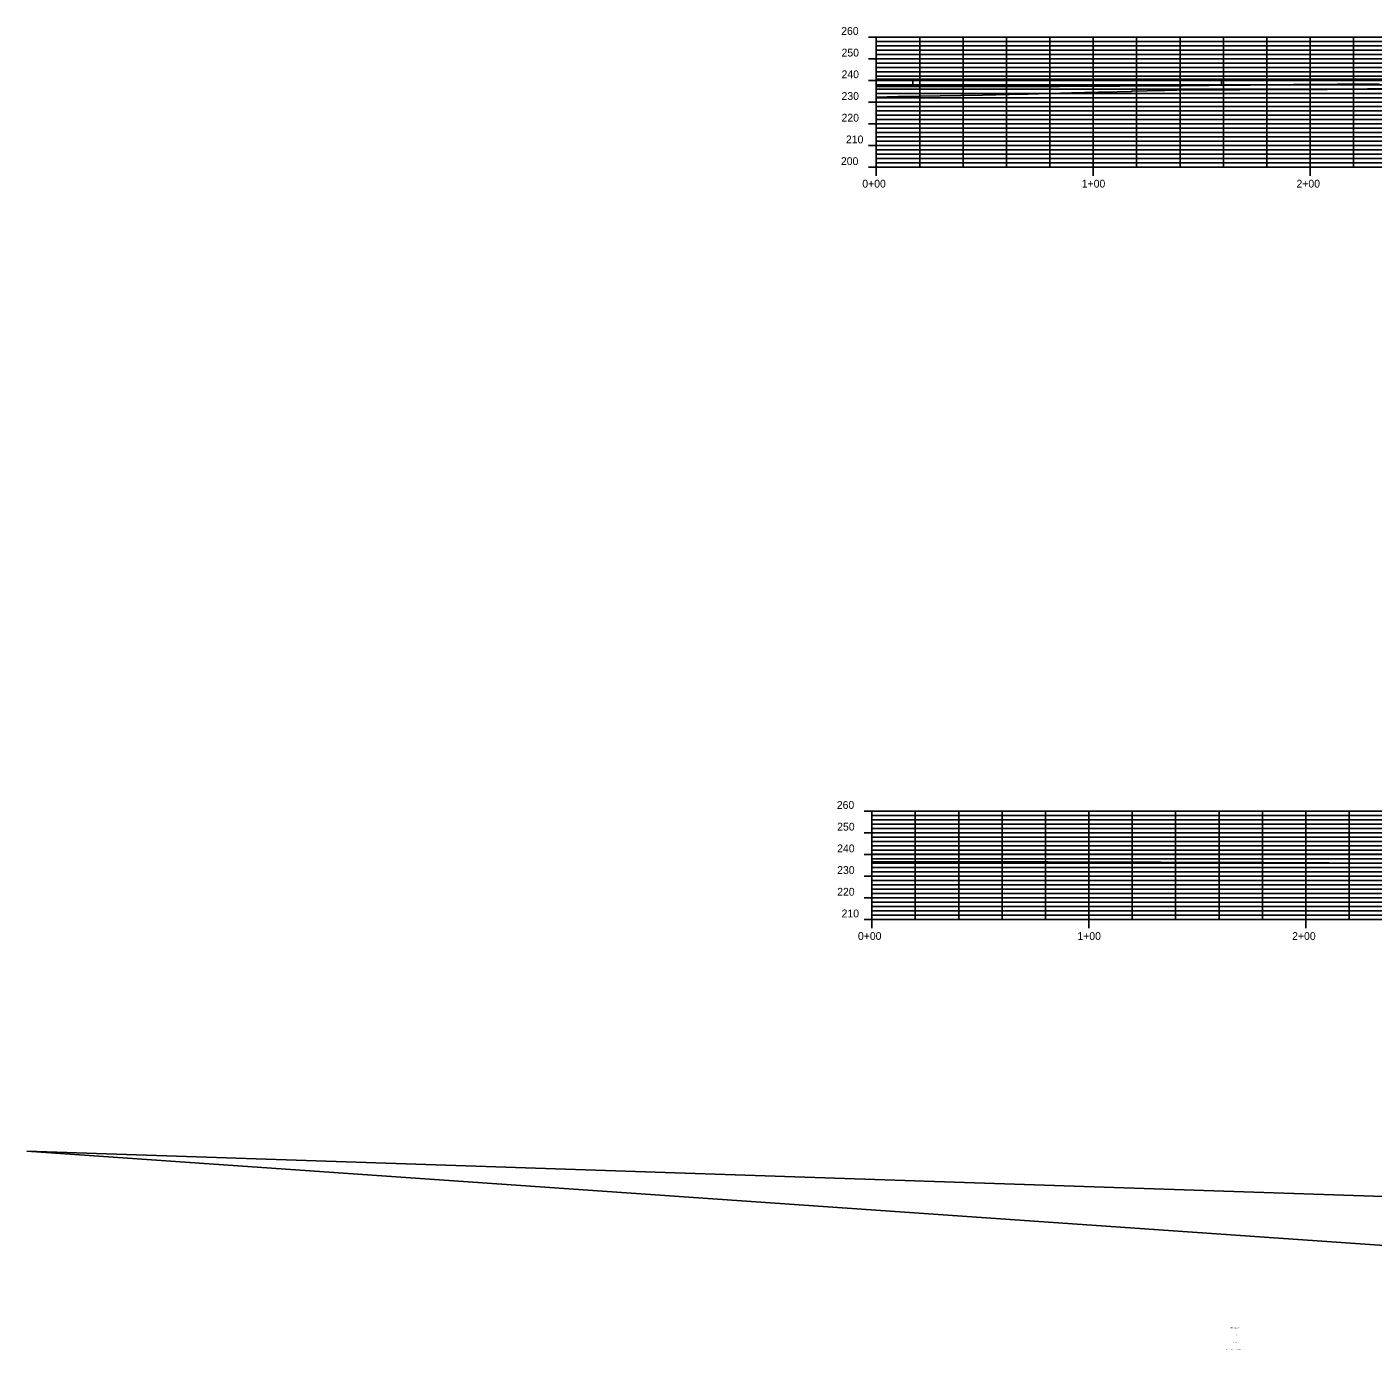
# Model space of a CAD drawing. Extents: x 977011 to 983719, y 1526280 to 1528290.
# Drawn here: x 977011 to 977632, y 1527680 to 1528290 of the extents above; entities that cross this region are included whole.
import ezdxf

# ---------------------------------------------------------------- set-up
doc = ezdxf.new("R2010")
doc.units = 0
for name, color, linetype in [('B_Concrete', 7, 'Continuous'), ('R_Axis', 7, 'Continuous'), ('R_Axis Annot', 7, 'Continuous'), ('R_Exist Surface', 7, 'Continuous'), ('R_Grid', 7, 'Continuous'), ('R_Vert Alg', 7, 'Continuous')]:
    doc.layers.add(name, color=color, linetype=linetype)

msp = doc.modelspace()

# ---------------------------------------------------------------- linework, layer by layer
at = {"layer": 'B_Concrete'}
for p, q in [((977402.95, 1528265.57), (977976.87, 1528265.62)), ((977402.95, 1528262.07), (977402.95, 1528265.57)), ((977419.82, 1528262.09), (977419.82, 1528264.76)), ((977562.03, 1528262.66), (977562.03, 1528265.33)), ((978067.84, 1527908.78), (977400.94, 1527908.34)), ((977400.94, 1527904.84), (977400.94, 1527908.34)), ((977011.43, 1527771.4), (977676.06, 1527749.18)), ((977676.72, 1527725.15), (977011.43, 1527771.4))]:
    msp.add_line(p, q, dxfattribs=at)
at = {"layer": 'R_Axis'}
for p, q in [((977402.95, 1528224.95), (977402.95, 1528284.95)), ((977402.95, 1528224.95), (978002.95, 1528224.95)), ((977400.94, 1527878.16), (977400.94, 1527928.16)), ((977400.94, 1527878.16), (978100.94, 1527878.16))]:
    msp.add_line(p, q, dxfattribs=at)
at = {"layer": 'R_Exist Surface'}
for points in [[(977402.95, 1528257.29), (977413.01, 1528257.5), (977423.35, 1528257.69), (977432.4, 1528257.82), (977441.87, 1528257.99), (977451.91, 1528258.14), (977464.26, 1528258.45), (977472.89, 1528258.65), (977487.9, 1528259.03), (977492.87, 1528259.15), (977505.2, 1528259.47), (977507.5, 1528259.51), (977520.39, 1528259.86), (977520.96, 1528259.92), (977534.73, 1528260.31), (977536.02, 1528260.35), (977547.2, 1528260.53), (977560.09, 1528260.58), (977563.18, 1528260.64), (977570.45, 1528260.62), (977576.87, 1528260.72), (977578.22, 1528260.7), (977592.31, 1528260.8), (977592.65, 1528260.8), (977593.75, 1528260.8), (977607.35, 1528260.81), (977610.8, 1528260.81), (977614.69, 1528260.84), (977620.87, 1528260.93), (977629.34, 1528261), (977637.08, 1528261.02)], [(977400.94, 1527904.84), (977401.53, 1527904.84), (977404.17, 1527904.83), (977416.54, 1527904.81), (977419.65, 1527904.8), (977431.56, 1527904.78), (977431.76, 1527904.78), (977434.59, 1527904.77), (977445.24, 1527904.76), (977446.5, 1527904.75), (977448.13, 1527904.75), (977461.51, 1527904.73), (977468.14, 1527904.73), (977473.58, 1527904.74), (977476.51, 1527904.73), (977479.11, 1527904.72), (977482.19, 1527904.71), (977491.61, 1527904.68), (977494.79, 1527904.67), (977503, 1527904.67), (977506.16, 1527904.67), (977506.62, 1527904.66), (977520.43, 1527904.61), (977521.63, 1527904.6), (977534.09, 1527904.55), (977536.65, 1527904.52), (977547.72, 1527904.48), (977551.66, 1527904.48), (977561.81, 1527904.45), (977566.67, 1527904.44), (977571.91, 1527904.43), (977581.6, 1527904.39), (977589.95, 1527904.36), (977596.61, 1527904.33), (977604.4, 1527904.29), (977611.62, 1527904.26), (977620.68, 1527904.21), (977626.63, 1527904.18), (977631.7, 1527904.16), (977641.64, 1527904.14)]]:
    msp.add_lwpolyline(points, dxfattribs=at)
at = {"layer": 'R_Grid'}
for p, q in [((977399.35, 1528284.95), (977402.95, 1528284.95)), ((977399.35, 1528284.95), (977402.95, 1528284.95)), ((977402.95, 1528284.95), (978002.95, 1528284.95)), ((977402.95, 1528284.95), (978002.95, 1528284.95)), ((977422.95, 1528224.95), (977422.95, 1528284.95)), ((977442.95, 1528224.95), (977442.95, 1528284.95)), ((977462.95, 1528224.95), (977462.95, 1528284.95)), ((977482.95, 1528224.95), (977482.95, 1528284.95)), ((977502.95, 1528224.95), (977502.95, 1528284.95)), ((977522.95, 1528224.95), (977522.95, 1528284.95)), ((977542.95, 1528224.95), (977542.95, 1528284.95)), ((977562.95, 1528224.95), (977562.95, 1528284.95)), ((977582.95, 1528224.95), (977582.95, 1528284.95)), ((977602.95, 1528224.95), (977602.95, 1528284.95)), ((977622.95, 1528224.95), (977622.95, 1528284.95)), ((977402.95, 1528282.95), (977404.75, 1528282.95)), ((977402.95, 1528282.95), (978002.95, 1528282.95)), ((977402.95, 1528280.95), (977404.75, 1528280.95)), ((977402.95, 1528280.95), (978002.95, 1528280.95)), ((977402.95, 1528278.95), (977404.75, 1528278.95)), ((977402.95, 1528278.95), (978002.95, 1528278.95)), ((977399.35, 1528274.95), (977402.95, 1528274.95)), ((977402.95, 1528276.95), (977404.75, 1528276.95)), ((977402.95, 1528276.95), (978002.95, 1528276.95)), ((977402.95, 1528274.95), (978002.95, 1528274.95)), ((977402.95, 1528272.95), (977404.75, 1528272.95)), ((977402.95, 1528272.95), (978002.95, 1528272.95)), ((977402.95, 1528270.95), (977404.75, 1528270.95)), ((977402.95, 1528270.95), (978002.95, 1528270.95)), ((977402.95, 1528268.95), (977404.75, 1528268.95)), ((977402.95, 1528268.95), (978002.95, 1528268.95)), ((977402.95, 1528266.95), (977404.75, 1528266.95)), ((977402.95, 1528266.95), (978002.95, 1528266.95)), ((977399.35, 1528264.95), (977402.95, 1528264.95)), ((977402.95, 1528264.95), (978002.95, 1528264.95)), ((977402.95, 1528262.95), (977404.75, 1528262.95)), ((977402.95, 1528262.95), (978002.95, 1528262.95)), ((977402.95, 1528260.95), (977404.75, 1528260.95)), ((977402.95, 1528260.95), (978002.95, 1528260.95)), ((977399.35, 1528254.95), (977402.95, 1528254.95)), ((977402.95, 1528258.95), (977404.75, 1528258.95)), ((977402.95, 1528258.95), (978002.95, 1528258.95)), ((977402.95, 1528256.95), (977404.75, 1528256.95)), ((977402.95, 1528256.95), (978002.95, 1528256.95)), ((977402.95, 1528254.95), (978002.95, 1528254.95)), ((977402.95, 1528252.95), (977404.75, 1528252.95)), ((977402.95, 1528252.95), (978002.95, 1528252.95)), ((977402.95, 1528250.95), (977404.75, 1528250.95)), ((977402.95, 1528250.95), (978002.95, 1528250.95)), ((977402.95, 1528248.95), (977404.75, 1528248.95)), ((977402.95, 1528248.95), (978002.95, 1528248.95)), ((977402.95, 1528246.95), (977404.75, 1528246.95)), ((977402.95, 1528246.95), (978002.95, 1528246.95)), ((977399.35, 1528244.95), (977402.95, 1528244.95)), ((977402.95, 1528244.95), (978002.95, 1528244.95)), ((977402.95, 1528242.95), (977404.75, 1528242.95)), ((977402.95, 1528242.95), (978002.95, 1528242.95)), ((977402.95, 1528240.95), (977404.75, 1528240.95)), ((977402.95, 1528240.95), (978002.95, 1528240.95)), ((977399.35, 1528234.95), (977402.95, 1528234.95)), ((977402.95, 1528238.95), (977404.75, 1528238.95)), ((977402.95, 1528238.95), (978002.95, 1528238.95)), ((977402.95, 1528236.95), (977404.75, 1528236.95)), ((977402.95, 1528236.95), (978002.95, 1528236.95)), ((977402.95, 1528234.95), (978002.95, 1528234.95)), ((977402.95, 1528232.95), (977404.75, 1528232.95)), ((977402.95, 1528232.95), (978002.95, 1528232.95)), ((977402.95, 1528230.95), (977404.75, 1528230.95)), ((977402.95, 1528230.95), (978002.95, 1528230.95)), ((977402.95, 1528228.95), (977404.75, 1528228.95)), ((977402.95, 1528228.95), (978002.95, 1528228.95)), ((977399.35, 1528224.95), (977402.95, 1528224.95)), ((977402.95, 1528226.95), (977404.75, 1528226.95)), ((977402.95, 1528226.95), (978002.95, 1528226.95)), ((977402.95, 1528220.95), (977402.95, 1528224.95)), ((977502.95, 1528220.95), (977502.95, 1528224.95)), ((977602.95, 1528220.95), (977602.95, 1528224.95)), ((977397.34, 1527928.16), (977400.94, 1527928.16)), ((977397.34, 1527928.16), (977400.94, 1527928.16)), ((977400.94, 1527928.16), (978100.94, 1527928.16)), ((977400.94, 1527928.16), (978100.94, 1527928.16)), ((977400.94, 1527926.16), (977402.74, 1527926.16)), ((977400.94, 1527926.16), (978100.94, 1527926.16)), ((977400.94, 1527924.16), (977402.74, 1527924.16)), ((977400.94, 1527924.16), (978100.94, 1527924.16)), ((977420.94, 1527878.16), (977420.94, 1527928.16)), ((977440.94, 1527878.16), (977440.94, 1527928.16)), ((977460.94, 1527878.16), (977460.94, 1527928.16)), ((977480.94, 1527878.16), (977480.94, 1527928.16)), ((977500.94, 1527878.16), (977500.94, 1527928.16)), ((977520.94, 1527878.16), (977520.94, 1527928.16)), ((977540.94, 1527878.16), (977540.94, 1527928.16)), ((977560.94, 1527878.16), (977560.94, 1527928.16)), ((977580.94, 1527878.16), (977580.94, 1527928.16)), ((977600.94, 1527878.16), (977600.94, 1527928.16)), ((977620.94, 1527878.16), (977620.94, 1527928.16)), ((977397.34, 1527918.16), (977400.94, 1527918.16)), ((977400.94, 1527922.16), (977402.74, 1527922.16)), ((977400.94, 1527922.16), (978100.94, 1527922.16)), ((977400.94, 1527920.16), (977402.74, 1527920.16)), ((977400.94, 1527920.16), (978100.94, 1527920.16)), ((977400.94, 1527918.16), (978100.94, 1527918.16)), ((977400.94, 1527916.16), (977402.74, 1527916.16)), ((977400.94, 1527916.16), (978100.94, 1527916.16)), ((977400.94, 1527914.16), (977402.74, 1527914.16)), ((977400.94, 1527914.16), (978100.94, 1527914.16)), ((977400.94, 1527912.16), (977402.74, 1527912.16)), ((977400.94, 1527912.16), (978100.94, 1527912.16)), ((977397.34, 1527908.16), (977400.94, 1527908.16)), ((977400.94, 1527910.16), (977402.74, 1527910.16)), ((977400.94, 1527910.16), (978100.94, 1527910.16)), ((977400.94, 1527908.16), (978100.94, 1527908.16)), ((977400.94, 1527906.16), (977402.74, 1527906.16)), ((977400.94, 1527906.16), (978100.94, 1527906.16)), ((977400.94, 1527904.16), (977402.74, 1527904.16)), ((977400.94, 1527904.16), (978100.94, 1527904.16)), ((977400.94, 1527902.16), (977402.74, 1527902.16)), ((977400.94, 1527902.16), (978100.94, 1527902.16)), ((977400.94, 1527900.16), (977402.74, 1527900.16)), ((977400.94, 1527900.16), (978100.94, 1527900.16)), ((977397.34, 1527898.16), (977400.94, 1527898.16)), ((977400.94, 1527898.16), (978100.94, 1527898.16)), ((977400.94, 1527896.16), (977402.74, 1527896.16)), ((977400.94, 1527896.16), (978100.94, 1527896.16)), ((977400.94, 1527894.16), (977402.74, 1527894.16)), ((977400.94, 1527894.16), (978100.94, 1527894.16)), ((977397.34, 1527888.16), (977400.94, 1527888.16)), ((977400.94, 1527892.16), (977402.74, 1527892.16)), ((977400.94, 1527892.16), (978100.94, 1527892.16)), ((977400.94, 1527890.16), (977402.74, 1527890.16)), ((977400.94, 1527890.16), (978100.94, 1527890.16)), ((977400.94, 1527888.16), (978100.94, 1527888.16)), ((977400.94, 1527886.16), (977402.74, 1527886.16)), ((977400.94, 1527886.16), (978100.94, 1527886.16)), ((977400.94, 1527884.16), (977402.74, 1527884.16)), ((977400.94, 1527884.16), (978100.94, 1527884.16)), ((977400.94, 1527882.16), (977402.74, 1527882.16)), ((977400.94, 1527882.16), (978100.94, 1527882.16)), ((977397.34, 1527878.16), (977400.94, 1527878.16)), ((977400.94, 1527880.16), (977402.74, 1527880.16)), ((977400.94, 1527880.16), (978100.94, 1527880.16)), ((977400.94, 1527874.16), (977400.94, 1527878.16)), ((977500.94, 1527874.16), (977500.94, 1527878.16)), ((977600.94, 1527874.16), (977600.94, 1527878.16))]:
    msp.add_line(p, q, dxfattribs=at)
at = {"layer": 'R_Vert Alg'}
msp.add_lwpolyline([(977402.95, 1528262.07), (977403.81, 1528262.07), (977404.5, 1528262.07), (977404.96, 1528262.08), (977411.17, 1528262.08), (977414.98, 1528262.08), (977421.39, 1528262.09), (977425, 1528262.1), (977428.46, 1528262.1), (977435.02, 1528262.11), (977435.63, 1528262.11), (977436.87, 1528262.11), (977442.44, 1528262.11), (977445.04, 1528262.12), (977446.31, 1528262.12), (977446.89, 1528262.12), (977449.38, 1528262.12), (977455.06, 1528262.13), (977462.28, 1528262.14), (977465.08, 1528262.14), (977467.76, 1528262.15), (977475.1, 1528262.17), (977476.06, 1528262.17), (977478.95, 1528262.18), (977483.66, 1528262.2), (977485.12, 1528262.2), (977487.41, 1528262.21), (977495.14, 1528262.24), (977503.18, 1528262.27), (977505.15, 1528262.28), (977506.46, 1528262.29), (977512.02, 1528262.32), (977514.62, 1528262.33), (977515.17, 1528262.33), (977520.93, 1528262.37), (977522.04, 1528262.37), (977522.54, 1528262.38), (977525.19, 1528262.39), (977533.85, 1528262.45), (977535.21, 1528262.46), (977544.07, 1528262.52), (977545.23, 1528262.53), (977546.35, 1528262.54), (977555.25, 1528262.61), (977556.17, 1528262.61), (977565.27, 1528262.69), (977571.72, 1528262.75), (977572.14, 1528262.75), (977572.32, 1528262.76), (977575.29, 1528262.78), (977584.97, 1528262.88), (977585.31, 1528262.88), (977585.64, 1528262.89), (977595.33, 1528262.99), (977595.47, 1528262.99), (977602.23, 1528263.06), (977605.29, 1528263.09), (977605.35, 1528263.09), (977605.42, 1528263.09), (977615.37, 1528263.18), (977621.97, 1528263.23), (977622.24, 1528263.23), (977622.36, 1528263.24), (977625.39, 1528263.26), (977634.76, 1528263.33)], dxfattribs=at)

# ---------------------------------------------------------------- texts
at = {"layer": 'B_Concrete'}
for s, p in [("OFFSET 1250' (UP)", (977566.09, 1527689.8)), ('LT. =665', (977567.36, 1527686.44)), ('RT. =575', (977567.37, 1527683.08)), ("FROM PT. 18' BACK FROM EDGE OF LANE", (977562.98, 1527679.72))]:
    msp.add_text(s, height=0.36, dxfattribs=at).set_placement(p)
at = {"layer": 'R_Axis Annot'}
for s, height, p in [('260', 3.6, (977386.76, 1528285.95)), ('260', 3.6, (977386.76, 1528285.95)), ('250', 3.6, (977386.93, 1528275.95)), ('240', 3.6, (977386.93, 1528265.95)), ('230', 3.6, (977386.93, 1528255.95)), ('220', 3.6, (977386.93, 1528245.95)), ('210', 3.6, (977388.97, 1528235.95)), ('200', 3.6, (977386.65, 1528225.95)), ('-', 0.0001, (977402.95, 1528224.95)), ('0+00', 3.6, (977396.5, 1528215.55)), ('1+00', 3.6, (977497.66, 1528215.55)), ('2+00', 3.6, (977596.64, 1528215.55)), ('260', 3.6, (977384.75, 1527929.16)), ('260', 3.6, (977384.75, 1527929.16)), ('250', 3.6, (977384.92, 1527919.16)), ('240', 3.6, (977384.92, 1527909.16)), ('230', 3.6, (977384.92, 1527899.16)), ('220', 3.6, (977384.92, 1527889.16)), ('210', 3.6, (977386.96, 1527879.16)), ('-', 0.0001, (977400.94, 1527878.16)), ('0+00', 3.6, (977394.49, 1527868.76)), ('1+00', 3.6, (977495.65, 1527868.76)), ('2+00', 3.6, (977594.63, 1527868.76))]:
    msp.add_text(s, height=height, dxfattribs=at).set_placement(p)

doc.saveas('drawing.dxf')
